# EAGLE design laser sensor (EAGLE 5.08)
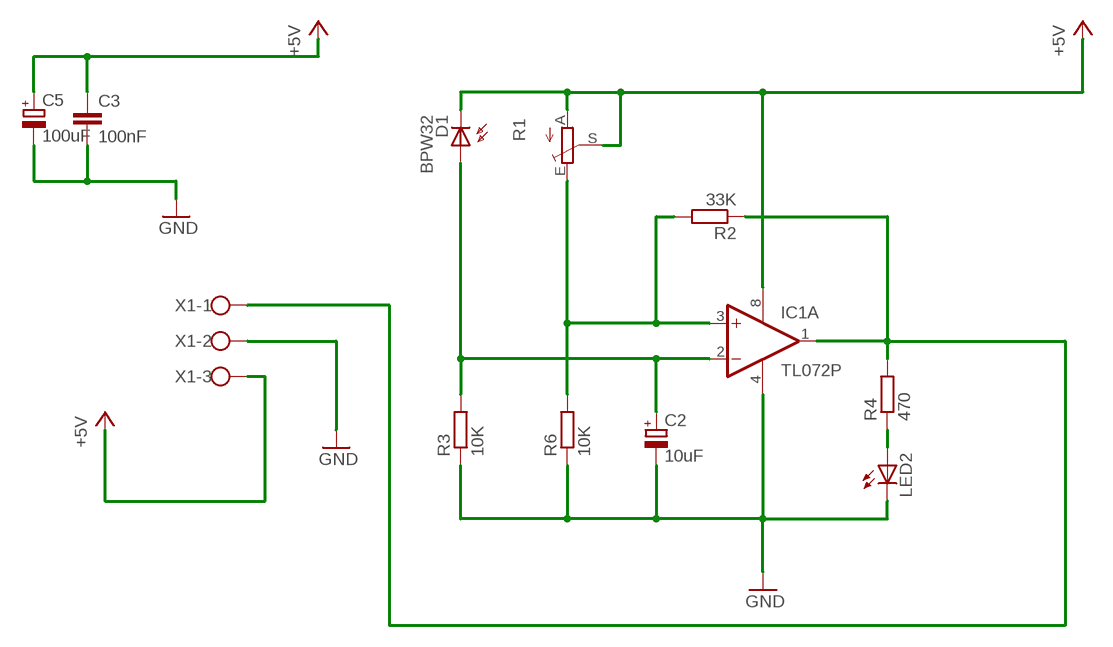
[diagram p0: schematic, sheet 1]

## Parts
C2  10uF  CPOL-EUE2.5-5  [E2,5-5]
C3  100nF  C-EU025-025X050  [C025-025X050]
C5  100uF  CPOL-EUE2,5-6E  [E2,5-6E]
D1  BPW32  [BPW32]
IC1  TL072P  [DIL08]
LED2  LED3MM  [LED3MM]
R1  TRIM_EU-CA6V  [CA6V]
R2  33K  R-EU_0207/2V  [0207/2V]
R3  10K  R-EU_0207/2V  [0207/2V]
R4  470  R-EU_0207/2V  [0207/2V]
R6  10K  R-EU_0207/2V  [0207/2V]
X1  W237-103  [W237-103]

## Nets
+5V: C3.1 C5.+ D1.K(C) IC1.8(P:V+) R1.A R1.S X1.3
GND: C2.- C3.2 C5.- IC1.4(P:V-) LED2.K(C) R3.1 R6.1 X1.2
N$1: IC1.3(A:+IN) R1.E R2.2 R6.2
N$2: IC1.1(A:OUT) R2.1 R4.2 X1.1
N$3: LED2.A R4.1
N$4: C2.+ D1.A IC1.2(A:-IN) R3.2
Unconnected: IC1.5(B:+IN) IC1.6(B:-IN) IC1.7(B:OUT)

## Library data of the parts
C2 C5 = rcl:CPOL-EU: POLARIZED CAPACITOR, European symbol
C3 = rcl:C-EU: CAPACITOR, European symbol
D1 = opto-trans-siemens:BPW32: PHOTO DIODE
IC1 = linear:TL072: OP AMP
LED2 = led:LED: LED
R1 = pot:TRIM_EU-: POTENTIOMETER
R2-R4 R6 = rcl:R-EU_: RESISTOR, European symbol
X1 = con-wago-500:W237-103: WAGO SCREW CLAMP

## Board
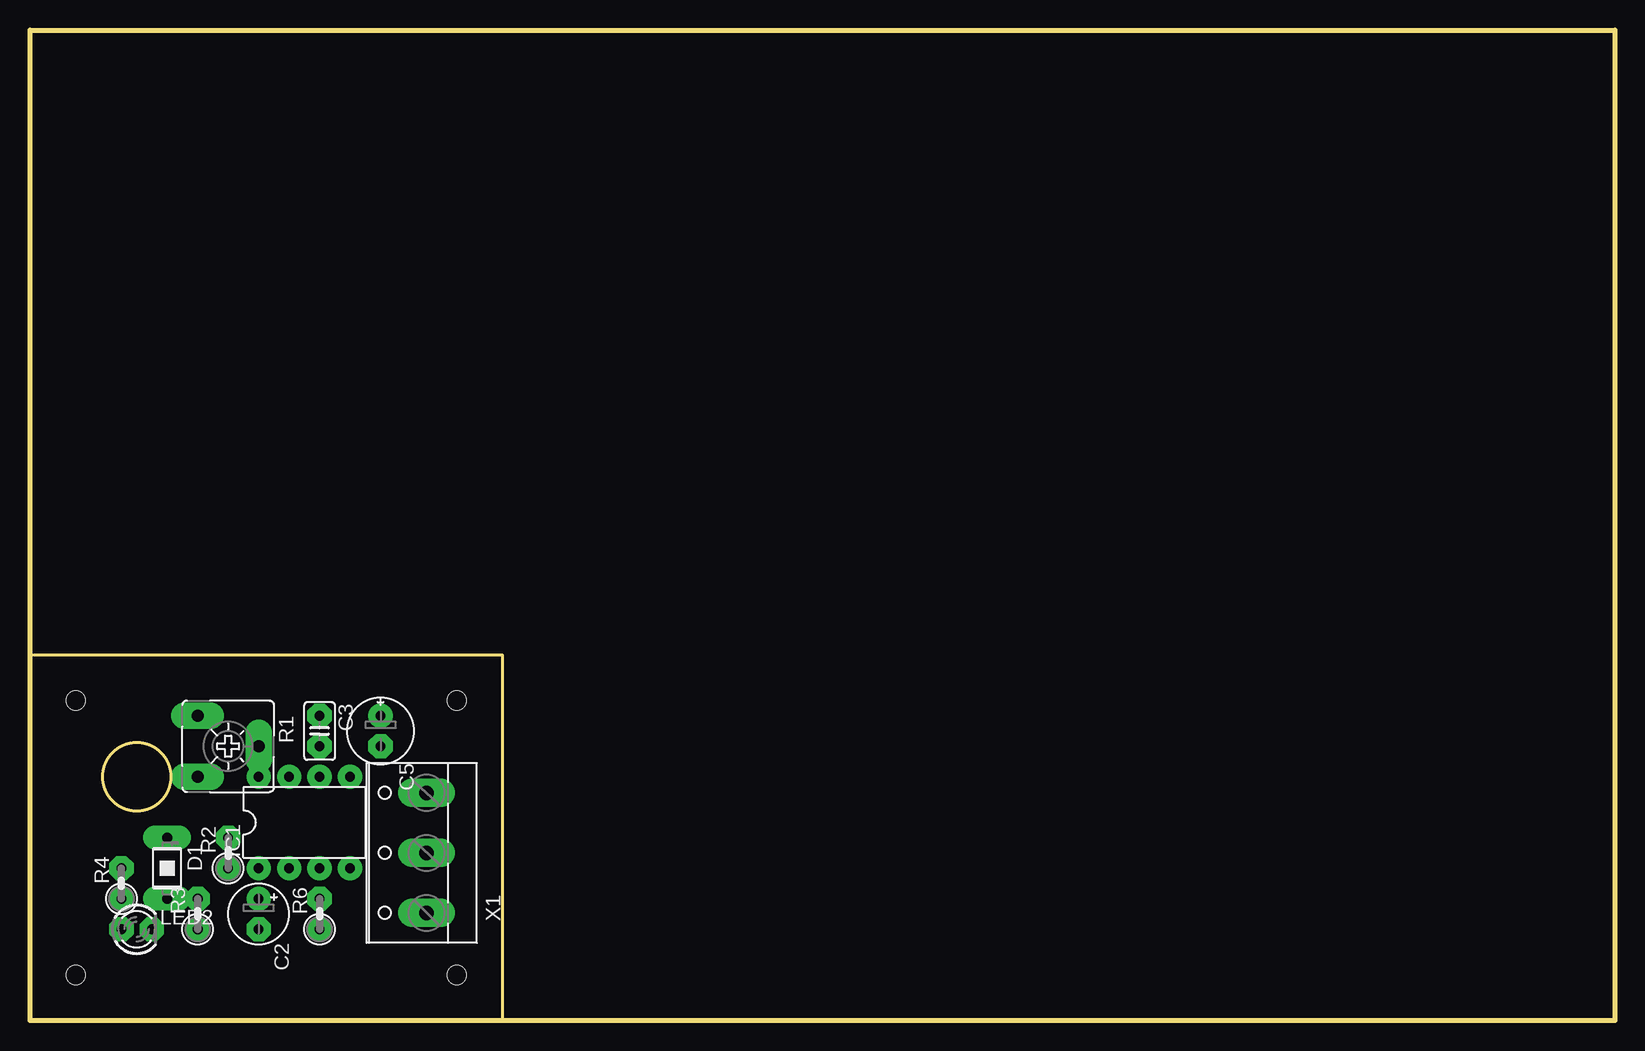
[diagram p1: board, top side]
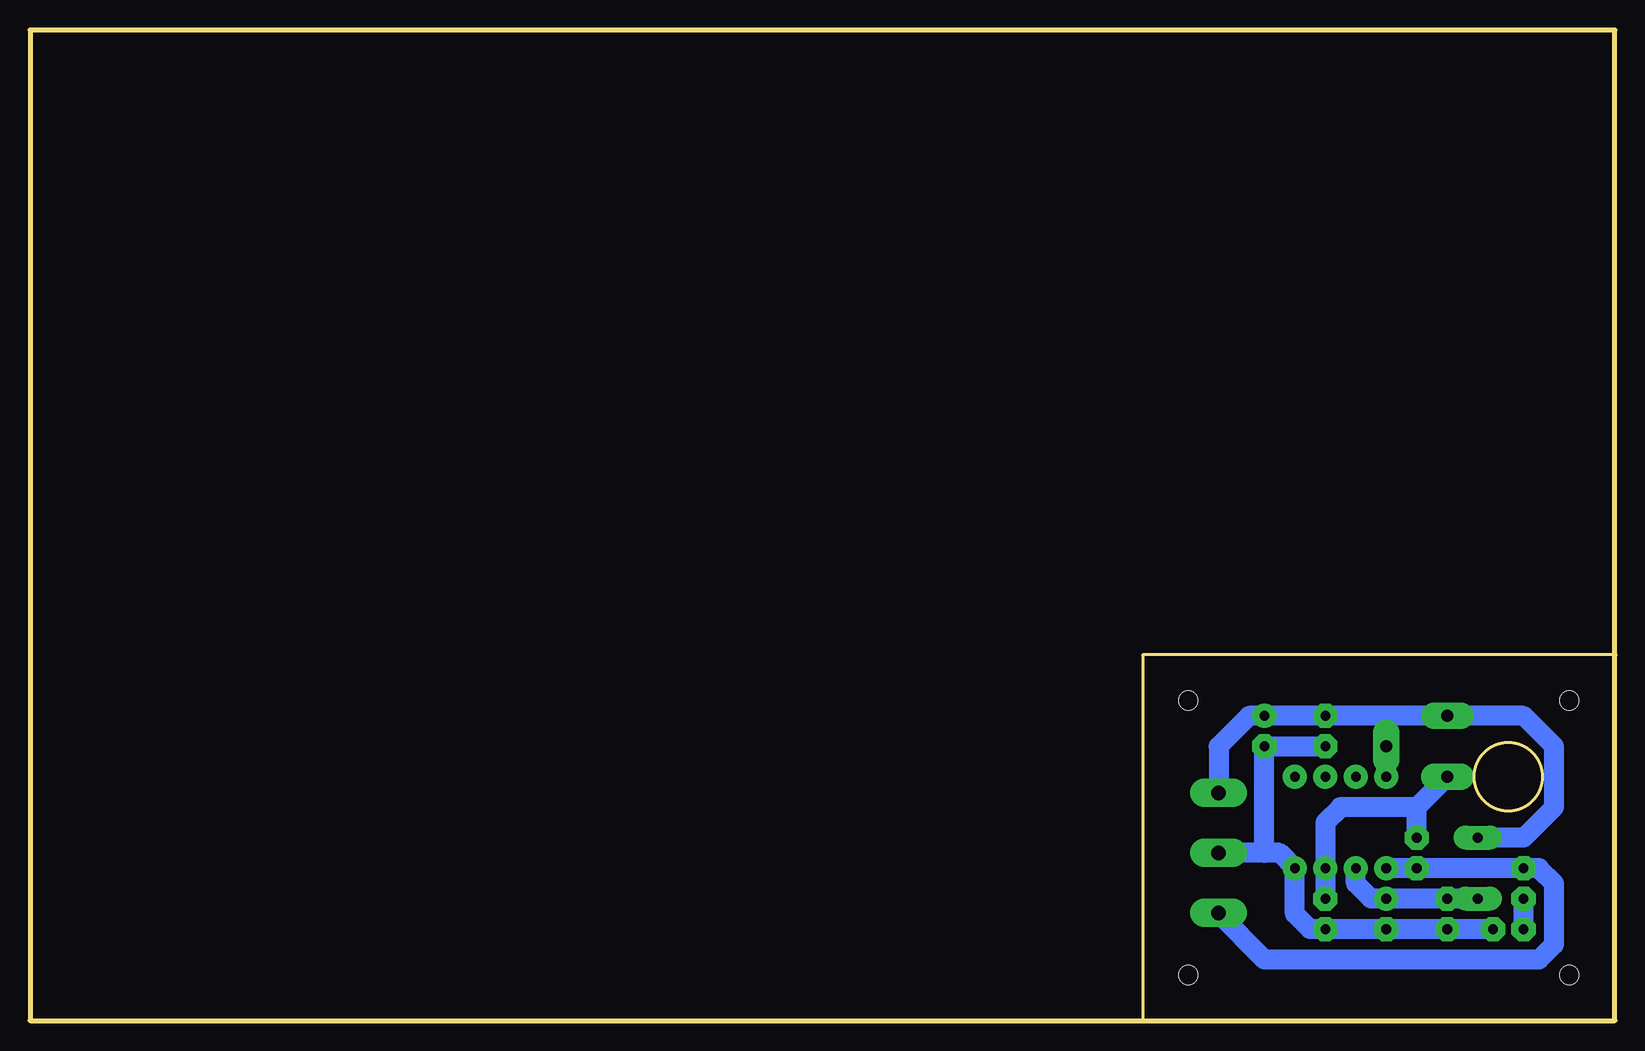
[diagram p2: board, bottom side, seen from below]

Size 132.08 x 82.55 mm. Coordinates in mm from the lower left corner, seen from the top.
Outline: 0,30.48 0,0 39.37,0
Outline: 0,30.48 0,82.55 132.08,82.55 132.08,0 39.37,0
Outline: 0,30.48 39.37,30.48 39.37,0
Outline: circle at 8.89,20.32 radius 2.84
Copper layers (1*16): Top 1mm / dielectric 1.5mm / Bottom 1mm
Design rules "DRC settings middle": minimum track width 1.2mm, minimum drill 24mil, track to track 0.4mm, track to pad 0.4mm, pad to pad 0.4mm, via to via 0.4mm, smd to smd 8mil, copper to edge 0.5mm, drill to drill 0.5mm, minimum pad ring 0.6mm, minimum via ring 1mm, stop-mask expansion 4mil, vias tented up to drill 0mil, thermal gap 10mil
Holes 1.6 mm at 3.81,3.81 3.81,26.67 35.56,26.67 35.56,3.81

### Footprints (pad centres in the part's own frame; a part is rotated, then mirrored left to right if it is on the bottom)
E2,5-5 = drill 0.813 pad 1.6 round: + -1.27,0 | drill 0.813 pad 1.6 octagon: - 1.27,0
C025-025X050 = drill 0.813 octagon: 1 -1.27,0; 2 1.27,0
E2,5-6E = drill 0.813 pad 1.575 round: + -1.27,0 | drill 0.813 pad 1.575 octagon: - 1.27,0
BPW32 = drill 0.813 long: A 0,2.54; K 0,-2.54
DIL08 = drill 0.813 pad 1.27 round: 1 -3.81,-3.81; 2 -1.27,-3.81; 3 1.27,-3.81; 4 3.81,-3.81; 5 3.81,3.81; 6 1.27,3.81; 7 -1.27,3.81; 8 -3.81,3.81
LED3MM = drill 0.813 octagon: A -1.27,0; K 1.27,0
CA6V = drill 1.016 long: A -2.54,-2.54; E 2.54,-2.54; S 0,2.54
0207/2V = drill 0.813 octagon: 1 -1.27,0; 2 1.27,0
W237-103 = drill 1.194 long: 1 -5,-1.29; 2 0,-1.29; 3 5,-1.29

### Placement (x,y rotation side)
C2  19.05,8.89 270 top
C3  24.13,24.13 270 top
C5  29.21,24.13 270 top
D1  11.43,12.7 180 top
IC1  22.86,16.51 0 top
LED2  8.89,7.62 0 top
R1  16.51,22.86 270 top
R2  16.51,13.97 90 top
R3  13.97,8.89 90 top
R4  7.62,11.43 90 top
R6  24.13,8.89 90 top
X1  31.75,13.97 90 top

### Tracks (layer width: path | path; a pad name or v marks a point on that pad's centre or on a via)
+5V
  Bottom 1.676: D1.K 7.62,15.24 5.08,17.78 5.08,22.86 7.62,25.4 R1.A 19.05,25.4 | IC1.8 R1.S 19.05,25.4 | 19.05,25.4 C3.1 C5.+ 30.48,25.4 33.02,22.86 33.02,18.99 X1.3
GND
  Bottom 1.676: C3.2 C5.- 29.21,13.97 | 29.21,13.97 27.94,13.97 IC1.4 26.67,8.89 25.4,7.62 R6.1 C2.- R3.1 LED2.K | 29.21,13.97 X1.2
N$1
  Bottom 1.676: 16.51,17.78 22.86,17.78 24.13,16.51 IC1.3 R6.2 | R2.2 16.51,17.78 | 16.51,17.78 R1.E
N$2
  Bottom 1.676: IC1.1 R2.1 R4.2 6.35,12.7 5.08,11.43 5.08,6.35 6.35,5.08 29.21,5.08 33.02,8.89 33.02,8.95 X1.1
N$3
  Bottom 1.676: LED2.A R4.1
N$4
  Bottom 1.676: R3.2 D1.A C2.+ 20.32,10.16 21.59,11.43 IC1.2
